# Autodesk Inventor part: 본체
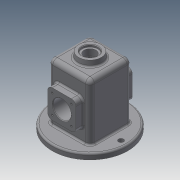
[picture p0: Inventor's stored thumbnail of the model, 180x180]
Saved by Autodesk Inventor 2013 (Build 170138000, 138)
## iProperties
Created: 2021-08
Part Number: 본체
Material: 일반
Document SubType Name: Modeling
Designer: a
Density: 1 g/cm^3
Author: a
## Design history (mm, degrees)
sketch "스케치1"
  geometry: L1 (-37, -37)-(37, -37); L2 (37, -37)-(37, 37); L3 (37, 37)-(-37, 37); L4 (-37, 37)-(-37, -37); L5 (-37, -37)-(37, 37); L6 (37, -37)-(-37, 37); 1 further point
  constraints: 12 end point, 2 midpoint, 2 parallel, 1 horizontal, 1 perpendicular
  dimensions: "d0" = 74 distance of L3.end L2.end; "d1" = 74 distance of L2.end L1.end
extrude "돌출1" new body sketch "스케치1" distance "d2" = 110; taper "d3" = 0 deg
feature "쉘1" dims "d4" = 5
sketch "스케치2"
  geometry: L1 (37, -37)-(-37, -37) reference; L2 (37, 37)-(37, -37) reference; L3 (-37, 37)-(37, 37) reference; L4 (-37, -37)-(-37, 37) reference; C1 r 67 at (0, 0); 1 further point
  constraints: 1 centre point, 1 coincident
  dimensions: "d5" = 134 diameter of C1
extrude "돌출2" join sketch "스케치2" distance "d6" = 10; taper "d7" = 0 deg
sketch "스케치3"
  geometry: L1 (104, -110)-(-30, -110) reference; L2 (12, -80)-(62, -80); L3 (62, -80)-(62, -30); L4 (62, -30)-(12, -30); L5 (12, -30)-(12, -80); L6 (12, -80)-(62, -30); L7 (62, -80)-(12, -30); 4 further points
  constraints: 12 end point, 4 midpoint, 2 parallel, 1 horizontal, 1 perpendicular, 1 vertical alignment
  dimensions: "d8" = 50 distance of L4.end L3.end; "d9" = 50 distance of L3.end L2.end; "d10" = 55 distance of point (37, -110) point (37, -55)
extrude "돌출3" join sketch "스케치3" distance "d11" = 13; taper "d12" = 0 deg
node "작업 평면1"
sketch "스케치6"
  geometry: C1 r 20 at (0, 0); 1 further point
  constraints: 1 centre point, 1 coincident
  dimensions: "d21" = 40 diameter of C1
extrude "돌출6" join sketch "스케치6" stored distance "d22" = 7; taper "d23" = 6 deg
sketch "스케치7"
  geometry: C1 r 20 at (0, 0) reference; 1 further point
  constraints: 1 coincident
hole "구멍1" sketch "스케치7" at (0, 0) diameter "d24" = 21; stored, may be unused: countersink angle "d28" = 90 deg, drill point angle "d30" = 0 deg; dims "d25" = 6, "d26" = 28, "d27" = 4, "d29" = 8
sketch "스케치10"
  geometry: L1 (37, 37)-(-37, 37) reference; L2 (0, 0)-(-55, 0); L3 (-55, 0)-(55, 0); C1 r 67 at (0, 0) reference; C2 r 4.5 at (-55, 0); C3 r 4.5 at (55, 0)
  constraints: 4 end point, 2 centre point, 2 coincident, 1 collinear, 1 parallel
  dimensions: "d46" = 55 distance of L2.start L2.end; "d47" = 110 distance of L2.end L3.end; "d48" = 9 diameter of C2; "d49" = 9 diameter of C3
extrude "돌출8" cut sketch "스케치10" stored distance "d50" = 7; taper "d51" = 0 deg
fillet "모깎기1" dims "d52" = 8
fillet "모깎기2" dims "d53" = 8
fillet "모깎기3" dims "d54" = 3
fillet "모깎기4" dims "d55" = 3
fillet "모깎기5" dims "d56" = 3
fillet "모깎기6" dims "d57" = 3
fillet "모깎기7" dims "d58" = 8
fillet "모깎기8" dims "d59" = 3
chamfer "모따기1" distance "d60" = 1; stored, may be unused: second distance "d61" = 2, angle "d62" = 45 deg
sketch "스케치11"
  geometry: L1 (58, 102)-(58, 0) reference; L2 (29, 0)-(29, 55); C1 r 25 at (29, 55)
  constraints: 2 end point, 1 centre point, 1 coincident, 1 parallel
  dimensions: "d63" = 55 distance of L2.start L2.end; "d64" = 50 diameter of C1
extrude "돌출9" join sketch "스케치11" distance "d65" = 7; taper "d66" = -20 deg
sketch "스케치12"
  geometry: L1 (12, -38)-(12, -72) reference; L2 (37, -110)-(37, -55); C1 r 16 at (37, -55)
  constraints: 2 end point, 1 centre point, 1 coincident, 1 parallel
  dimensions: "d67" = 55 distance of L2.start L2.end; "d68" = 32 diameter of C1
extrude "돌출10" cut sketch "스케치12" stored distance "d69" = 7; taper "d70" = 0 deg
sketch "스케치13"
  geometry: A1 r 8 centre (20, -72) between (12, -72) and (20, -80) reference; A2 r 8 centre (54, -72) between (54, -80) and (62, -72) reference; A3 r 8 centre (54, -38) between (62, -38) and (54, -30) reference; A4 r 8 centre (20, -38) between (20, -30) and (12, -38) reference; 5 further points
  constraints: 4 coincident
hole "구멍3" sketch "스케치13" at (20, -38), (20, -72), (54, -72), (54, -38) diameter "d71" = 3.242; stored, may be unused: countersink angle "d75" = 90 deg, drill point angle "d77" = 118 deg; dims "d72" = 8, "d73" = 28, "d74" = 4, "d76" = 10
sketch "스케치14"
  geometry: L1 (9, 18)-(49, 18) reference; L2 (-8, 0)-(-8, -89) reference; 2 further points
  constraints: 1 other
  dimensions: "d78" = 28 distance from line of point (29, -10) L1; "d79" = 37 distance from line of L2 point (29, -10)
feature "엠보싱1" sketch "스케치14" dims "d0" = 74, "d1" = 74, "d80" = 0.5, "d81" = 0
chamfer "모따기2" distance "d82" = 1; stored, may be unused: second distance "d83" = 2, angle "d84" = 45 deg
node "솔리드1"
mirror "대칭1"
mirror "대칭4"
mirror "대칭5"
